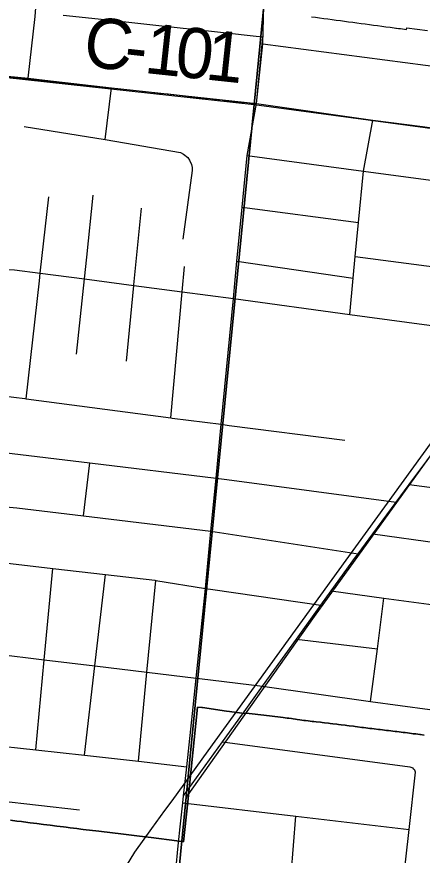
# Model space of a CAD drawing. Extents: x 0 to 34, y 0 to 22.
# Drawn here: x 3.3464 to 3.5761, y 20.0714 to 20.546 of the extents above; entities that cross this region are included whole.
import ezdxf

# ---------------------------------------------------------------- set-up
doc = ezdxf.new("R2010")
doc.units = 0
for name, color, linetype in [('GM_X_City_Street', 7, 'Continuous'), ('GM_X_Corporation', 7, 'Continuous'), ('GM_X_County_Road', 7, 'Continuous'), ('GM_X_County_Road_Text', 7, 'Continuous'), ('GM_X_Rail_Line', 7, 'Continuous'), ('GM_X_Section', 7, 'Continuous'), ('GM_X_State_Shield', 7, 'Continuous'), ('GM_X_Township_Road', 7, 'Continuous')]:
    doc.layers.add(name, color=color, linetype=linetype)

msp = doc.modelspace()

# ---------------------------------------------------------------- linework, layer by layer
at = {"layer": 'GM_X_City_Street'}
for p, q in [((3.39644, 20.4766), (3.40014, 20.50579)), ((3.47408, 20.43833), (3.53995, 20.42955)), ((3.47114, 20.40766), (3.53696, 20.39808)), ((3.53811, 20.41023), (3.6157, 20.40006)), ((3.3843, 20.26347), (3.38781, 20.29356)), ((3.50488, 20.1938), (3.55065, 20.18824)), ((3.32641, 20.10349), (3.382, 20.09707)), ((3.50144, 20.05675), (3.50453, 20.09347))]:
    msp.add_line(p, q, dxfattribs=at)
for points in [[(3.48588, 20.53071), (3.57795, 20.51863), (3.66805, 20.50681), (3.67572, 20.50581), (3.71213, 20.50103)], [(3.35054, 20.48381), (3.39644, 20.4766), (3.4391, 20.46909), (3.4409, 20.46825), (3.44333, 20.46628), (3.44429, 20.46478), (3.44537, 20.46238), (3.44579, 20.46068), (3.44582, 20.45897), (3.4405, 20.42008)], [(3.53501, 20.37758), (3.53696, 20.39808), (3.53811, 20.41023), (3.53995, 20.42955), (3.54272, 20.45867), (3.54802, 20.48745)], [(3.47689, 20.46757), (3.54272, 20.45867), (3.62057, 20.44815), (3.62367, 20.44773), (3.67428, 20.44088)], [(3.35171, 20.32977), (3.35928, 20.39648), (3.35978, 20.40088), (3.36469, 20.44414)], [(3.38024, 20.35507), (3.38474, 20.39762), (3.38605, 20.41001), (3.38974, 20.44498)], [(3.40858, 20.35108), (3.41278, 20.39395), (3.41282, 20.39434), (3.41705, 20.4376)], [(3.21916, 20.40215), (3.23425, 20.40753), (3.2371, 20.40786), (3.24088, 20.4074), (3.2596, 20.40559), (3.28413, 20.40322), (3.31193, 20.40052), (3.32799, 20.39897), (3.32888, 20.39907), (3.32996, 20.39934), (3.3309, 20.39967), (3.332, 20.40022), (3.33583, 20.40223), (3.3375, 20.40264), (3.33907, 20.40292), (3.34176, 20.40298), (3.34514, 20.4028), (3.35978, 20.40088), (3.38474, 20.39762), (3.41278, 20.39395), (3.44014, 20.39037), (3.46912, 20.38658), (3.53501, 20.37758), (3.61236, 20.36702)], [(3.43371, 20.31898), (3.44014, 20.39037), (3.44143, 20.40468)], [(3.21485, 20.34622), (3.2768, 20.33885), (3.33849, 20.33151), (3.35106, 20.32986), (3.35171, 20.32977), (3.43371, 20.31898), (3.4345, 20.31887), (3.46224, 20.31533), (3.46673, 20.31475), (3.53222, 20.30638)], [(3.21272, 20.31477), (3.27324, 20.30744), (3.33908, 20.29946), (3.38781, 20.29356), (3.45931, 20.2849), (3.46543, 20.28408), (3.56134, 20.27126)], [(3.20891, 20.28431), (3.26979, 20.27707), (3.34225, 20.26847), (3.34646, 20.26797), (3.3843, 20.26347), (3.45642, 20.2549), (3.5397, 20.2421)], [(3.56871, 20.28118), (3.63474, 20.27251), (3.6772, 20.26693), (3.6788, 20.26672), (3.73384, 20.25949), (3.77387, 20.25423), (3.77528, 20.25405), (3.82892, 20.247)], [(3.54801, 20.25329), (3.5861, 20.24799), (3.59232, 20.24649), (3.60869, 20.2415), (3.61265, 20.24082), (3.63138, 20.23843), (3.67276, 20.23314), (3.72928, 20.22591), (3.76967, 20.22075), (3.77143, 20.22052), (3.82521, 20.21365)], [(3.33964, 20.23697), (3.36691, 20.2338), (3.39666, 20.23033), (3.42457, 20.22708), (3.42515, 20.22699), (3.45327, 20.22238), (3.45746, 20.22178), (3.51862, 20.21287)], [(3.35721, 20.13107), (3.36202, 20.18201), (3.36691, 20.2338)], [(3.38483, 20.12799), (3.39068, 20.17854), (3.39666, 20.23033)], [(3.41535, 20.12459), (3.42017, 20.17497), (3.42515, 20.22699)], [(3.52455, 20.22111), (3.55434, 20.217), (3.58829, 20.21231), (3.65557, 20.20303), (3.65719, 20.20281), (3.72613, 20.19437)], [(3.54684, 20.15851), (3.55065, 20.18824), (3.55434, 20.217)], [(3.33434, 20.18537), (3.36202, 20.18201), (3.39068, 20.17854), (3.42017, 20.17497), (3.44797, 20.1716), (3.44993, 20.17137), (3.48561, 20.16705), (3.54684, 20.15851), (3.58031, 20.15385), (3.64863, 20.14432), (3.73579, 20.13218)], [(3.32929, 20.13418), (3.35721, 20.13107), (3.38483, 20.12799), (3.41535, 20.12459), (3.44269, 20.12154)], [(3.46291, 20.13552), (3.56898, 20.12144), (3.57068, 20.12085)], [(3.56391, 20.05071), (3.56461, 20.05209), (3.5651, 20.05411), (3.5686, 20.08593), (3.57216, 20.11835), (3.57187, 20.11951), (3.57139, 20.12018), (3.57068, 20.12085)], [(3.4405, 20.101), (3.50453, 20.09347), (3.5686, 20.08593)]]:
    msp.add_lwpolyline(points, dxfattribs=at)
at = {"layer": 'GM_X_Corporation'}
for points in [[(3.30016, 20.5166), (3.4228, 20.50337), (3.4275, 20.50285), (3.4322, 20.50233), (3.44161, 20.50128), (3.45301, 20.50001), (3.45336, 20.49997), (3.45585, 20.49969), (3.45814, 20.49944), (3.45954, 20.49928), (3.46045, 20.49918), (3.46282, 20.49891), (3.4651, 20.49866), (3.46711, 20.49844), (3.47171, 20.49792), (3.4765, 20.49739), (3.48217, 20.49677), (3.48578, 20.53448), (3.48202, 20.53489), (3.4635, 20.5369), (3.44465, 20.53894), (3.44074, 20.53937), (3.39618, 20.5442), (3.37281, 20.54673)], [(3.51328, 20.54606), (3.51562, 20.54575), (3.51797, 20.54543), (3.52032, 20.54512), (3.52266, 20.5448), (3.52501, 20.54449), (3.52735, 20.54417), (3.5297, 20.54386), (3.53205, 20.54354), (3.53439, 20.54323), (3.53674, 20.54291), (3.53909, 20.54259), (3.54143, 20.54228), (3.54378, 20.54196), (3.54613, 20.54165), (3.54847, 20.54133), (3.55082, 20.54102), (3.55316, 20.5407), (3.55551, 20.54039), (3.55786, 20.54007), (3.5602, 20.53975), (3.56111, 20.53963), (3.56142, 20.53959), (3.56255, 20.53944), (3.56372, 20.53928), (3.5649, 20.53912), (3.56724, 20.53881), (3.56733, 20.53975), (3.57907, 20.53817)], [(3.34283, 20.09123), (3.34655, 20.09076), (3.34919, 20.09043), (3.35034, 20.09028), (3.35407, 20.08981), (3.35786, 20.08933), (3.36158, 20.08885), (3.36537, 20.08837), (3.3691, 20.0879), (3.37288, 20.08742), (3.37438, 20.08723), (3.37661, 20.08694), (3.3804, 20.08646), (3.38264, 20.08618), (3.38409, 20.08601), (3.39289, 20.085), (3.40691, 20.08339), (3.41604, 20.08219), (3.4225, 20.08143), (3.43715, 20.07952), (3.43797, 20.07942), (3.44091, 20.07908), (3.4433, 20.10171), (3.44874, 20.15531), (3.45116, 20.15503), (3.45158, 20.15498), (3.46526, 20.15302), (3.46686, 20.15279), (3.46825, 20.15261), (3.47254, 20.15208), (3.47394, 20.15191), (3.4781, 20.15168), (3.4864, 20.15066), (3.49106, 20.15008), (3.49577, 20.1495), (3.49727, 20.14932), (3.49964, 20.14902), (3.50047, 20.14892), (3.50194, 20.14874), (3.50303, 20.1486), (3.50429, 20.14845), (3.50518, 20.14831), (3.50668, 20.14807), (3.50903, 20.1477), (3.50987, 20.1476), (3.51138, 20.14743), (3.51374, 20.14716), (3.51459, 20.14708), (3.51605, 20.14693), (3.51844, 20.14668), (3.5193, 20.1466), (3.52063, 20.14643), (3.52307, 20.14613), (3.52401, 20.14601), (3.5255, 20.14583), (3.52778, 20.14555), (3.52866, 20.14544), (3.53012, 20.14526), (3.53247, 20.14497), (3.53337, 20.14486), (3.53472, 20.14469), (3.53714, 20.14439), (3.53807, 20.14428), (3.53949, 20.1441), (3.54183, 20.14381), (3.54278, 20.1437), (3.54415, 20.14353), (3.54648, 20.14324), (3.54748, 20.14312), (3.54888, 20.14294), (3.55121, 20.14266), (3.55219, 20.14256), (3.55354, 20.14239), (3.55587, 20.1421), (3.55695, 20.14197), (3.55834, 20.14179), (3.55945, 20.14166), (3.56072, 20.1415), (3.5616, 20.14139), (3.56292, 20.14123), (3.56531, 20.14093), (3.56631, 20.14081), (3.5677, 20.14064), (3.57002, 20.14035), (3.57101, 20.14023), (3.57235, 20.14006), (3.57472, 20.13977), (3.57512, 20.13972), (3.57716, 20.13947)], [(3.57716, 20.13947), (3.57512, 20.13972), (3.57472, 20.13977), (3.57235, 20.14006), (3.57101, 20.14023), (3.57002, 20.14035), (3.5677, 20.14064), (3.56631, 20.14081), (3.56531, 20.14093), (3.56292, 20.14123), (3.5616, 20.14139), (3.56072, 20.1415), (3.55834, 20.14179), (3.55695, 20.14197), (3.55587, 20.1421), (3.55354, 20.14239), (3.55219, 20.14256), (3.55121, 20.14266), (3.54888, 20.14294), (3.54748, 20.14312), (3.54648, 20.14324), (3.54415, 20.14353), (3.54278, 20.1437), (3.54183, 20.14381), (3.53949, 20.1441), (3.53807, 20.14428), (3.53714, 20.14439), (3.53472, 20.14469), (3.53337, 20.14486), (3.53247, 20.14497), (3.53012, 20.14526), (3.52866, 20.14544), (3.52778, 20.14555), (3.5255, 20.14583), (3.52401, 20.14601), (3.52307, 20.14613), (3.52063, 20.14643), (3.5193, 20.1466), (3.51844, 20.14668), (3.51605, 20.14693), (3.51459, 20.14708), (3.51374, 20.14716), (3.51138, 20.14743), (3.50987, 20.1476), (3.50903, 20.1477), (3.50668, 20.14807), (3.50518, 20.14831), (3.50429, 20.14845), (3.50303, 20.1486), (3.50194, 20.14874), (3.50047, 20.14892), (3.49964, 20.14902), (3.49727, 20.14932), (3.49577, 20.1495), (3.49106, 20.15008), (3.4864, 20.15066), (3.4781, 20.15168), (3.47394, 20.15191), (3.47254, 20.15208), (3.46825, 20.15261), (3.46686, 20.15279), (3.46526, 20.15302), (3.45158, 20.15498), (3.45116, 20.15503), (3.44874, 20.15531), (3.4433, 20.10171), (3.44091, 20.07908), (3.43797, 20.07942), (3.43715, 20.07952), (3.4225, 20.08143), (3.41604, 20.08219), (3.40691, 20.08339), (3.39289, 20.085), (3.38409, 20.08601), (3.38264, 20.08618), (3.3804, 20.08646), (3.37661, 20.08694), (3.37438, 20.08723), (3.37288, 20.08742), (3.3691, 20.0879), (3.36537, 20.08837), (3.36158, 20.08885), (3.35786, 20.08933), (3.35407, 20.08981), (3.35034, 20.09028), (3.34919, 20.09043), (3.34655, 20.09076), (3.34283, 20.09123)]]:
    msp.add_lwpolyline(points, dxfattribs=at)
at = {"layer": 'GM_X_County_Road'}
for p, q in [((3.48588, 20.53071), (3.48633, 20.55224)), ((3.48218, 20.49699), (3.48588, 20.53071)), ((3.44537, 20.14644), (3.44589, 20.15158)), ((3.43811, 20.07849), (3.43907, 20.08749))]:
    msp.add_line(p, q, dxfattribs=at)
for points in [[(3.32159, 20.51431), (3.35287, 20.51121), (3.36233, 20.51012)], [(3.47426, 20.15128), (3.48561, 20.16705), (3.50488, 20.1938), (3.51862, 20.21287), (3.52455, 20.22111), (3.53826, 20.24016), (3.5397, 20.2421), (3.54801, 20.25329), (3.56134, 20.27126), (3.56871, 20.28118), (3.58864, 20.30803), (3.60861, 20.33494), (3.61756, 20.347), (3.63007, 20.3646), (3.65394, 20.39821), (3.66289, 20.41081), (3.67773, 20.43171), (3.68686, 20.44693), (3.68966, 20.45235), (3.69697, 20.4674), (3.71213, 20.50103), (3.71615, 20.5107), (3.71812, 20.51544)], [(3.36233, 20.51012), (3.40014, 20.50579), (3.48218, 20.49699)], [(3.44589, 20.15158), (3.44626, 20.15519), (3.44797, 20.1716), (3.45327, 20.22238), (3.45455, 20.23465), (3.45582, 20.24872), (3.45642, 20.2549), (3.45931, 20.2849), (3.46224, 20.31533), (3.46912, 20.38658), (3.47114, 20.40766), (3.47408, 20.43833), (3.47689, 20.46757), (3.48218, 20.49699)], [(3.48218, 20.49699), (3.54802, 20.48745), (3.57614, 20.48392), (3.62447, 20.4771), (3.665, 20.47184), (3.68222, 20.46945)], [(3.44093, 20.10499), (3.46291, 20.13552), (3.47426, 20.15128)], [(3.43907, 20.08749), (3.4405, 20.101), (3.44093, 20.10499), (3.44269, 20.12154), (3.445, 20.14284), (3.44537, 20.14644)], [(3.43079, 19.97786), (3.42944, 19.98608), (3.43678, 20.0647), (3.43773, 20.07488), (3.43811, 20.07849)]]:
    msp.add_lwpolyline(points, dxfattribs=at)
at = {"layer": 'GM_X_Rail_Line'}
for points in [[(3.35575, 19.94962), (3.41629, 19.97699), (3.43019, 19.97925), (3.44264, 20.1043), (3.51501, 20.20651), (3.65245, 20.39665), (3.68543, 20.44301), (3.698, 20.46736), (3.7522, 20.59859), (3.84096, 20.81312), (3.87665, 20.9)], [(3.4086, 20.0654), (3.41331, 20.07308), (3.42295, 20.08652), (3.43037, 20.09669), (3.43439, 20.10214), (3.45485, 20.13044), (3.52895, 20.23293), (3.58621, 20.31183), (3.63103, 20.37371), (3.65752, 20.41019), (3.67043, 20.42809), (3.67624, 20.4366), (3.68139, 20.44493), (3.69087, 20.46268), (3.69845, 20.48058), (3.70901, 20.50572), (3.74117, 20.58323), (3.76697, 20.64532), (3.83893, 20.81927), (3.85507, 20.85846), (3.87235, 20.9)]]:
    msp.add_lwpolyline(points, dxfattribs=at)
at = {"layer": 'GM_X_Section'}
for points in [[(2.98861, 20.55012), (3.4808, 20.49635), (3.43084, 19.98722), (2.94009, 20.04644)], [(3.4808, 20.49635), (4.00293, 20.42622), (3.95103, 19.92358), (3.43084, 19.98722)]]:
    msp.add_lwpolyline(points, close=True, dxfattribs=at)
at = {"layer": 'GM_X_State_Shield'}
for points in [[(3.52038, 20.9), (3.02189, 20.9), (2.98861, 20.55012), (3.4808, 20.49635)], [(4.05097, 20.9), (3.52038, 20.9), (3.4808, 20.49635), (4.00293, 20.42622)]]:
    msp.add_lwpolyline(points, close=True, dxfattribs=at)
at = {"layer": 'GM_X_Township_Road'}
msp.add_lwpolyline([(3.35287, 20.51121), (3.35684, 20.54619), (3.36228, 20.61706), (3.36576, 20.64296), (3.37307, 20.72241), (3.38075, 20.79559)], dxfattribs=at)

# ---------------------------------------------------------------- texts
at = {"layer": 'GM_X_County_Road_Text'}
for s, rotation, p in [('C', 353.5951, (3.38341, 20.51814)), ('1', 353.8719, (3.41807, 20.51429)), ('0', 353.8802, (3.43534, 20.51244)), ('1', 353.8804, (3.4526, 20.51059)), ('-', 353.8022, (3.40654, 20.51555))]:
    msp.add_text(s, height=0.02841, rotation=rotation, dxfattribs=at).set_placement(p)

doc.saveas('drawing.dxf')
